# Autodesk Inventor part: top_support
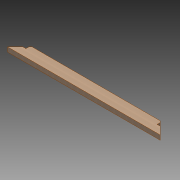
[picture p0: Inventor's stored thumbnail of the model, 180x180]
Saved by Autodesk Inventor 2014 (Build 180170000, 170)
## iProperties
Created: 2014-05
Part Number: top_support
Material: Maple
Document SubType Name: Modeling
Designer: t_emanb
Density: 1 g/cm^3
Appearance: Maple - Solid Natural Medium Gloss
Author: t_emanb
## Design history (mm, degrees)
sketch "Sketch1"
  geometry: L1 (0, 0)-(635, 0); L2 (635, 0)-(635, 635); L3 (635, 635)-(0, 635); L4 (0, 635)-(0, 0)
  constraints: 8 end point, 2 parallel, 1 horizontal, 1 perpendicular
  dimensions: "d0" = 635 distance of L1.start L1.end (= d1); "d1" = 635 distance of L3.end L1.start
extrude "Extrusion1" new body sketch "Sketch1" distance "d2" = 19.05; taper "d3" = 0 deg
sketch "Sketch2"
  geometry: L1 (0, 0)-(-635, 0) reference; L2 (-635, 0)-(-635, -635) reference; L3 (-635, -635)-(0, -635) reference; L4 (0, -635)-(0, 0) reference; L5 (-584.2, -50.8)-(-50.8, -50.8); L6 (-50.8, -50.8)-(-50.8, -584.2); L7 (-50.8, -584.2)-(-584.2, -584.2); L8 (-584.2, -584.2)-(-584.2, -50.8)
  constraints: 8 end point, 3 other
  dimensions: "d4" = 533.4 distance of L5.end L6.end
extrude "Extrusion2" cut sketch "Sketch2" stored distance "d5" = 12.7; taper "d6" = 0 deg
sketch "Sketch4"
  geometry: L1 (-584.2, -584.2)-(-584.2, -50.8) reference; L2 (-584.2, -50.8)-(-50.8, -50.8) reference; L3 (-50.8, -50.8)-(-50.8, -584.2) reference; L4 (0, 0)-(-635, 0) reference; L5 (-635, 0)-(-635, -635) reference; L6 (0, -635)-(0, 0) reference; L7 (-635, -635)-(-584.2, -584.2); L8 (-50.8, -584.2)-(0, -635)
  constraints: 4 end point, 1 perpendicular
extrude "Extrusion4" cut sketch "Sketch4" stored distance "d12" = 12.7; taper "d13" = 0 deg
workplane "Work Plane2"
  workplane "Work Plane1"
sketch "Sketch6"
  geometry: L1 (0, -50.8)-(0, 0) reference; L2 (19.05, -50.8)-(0, -50.8) reference; L3 (19.05, 0)-(19.05, -50.8) reference; L4 (0, 0)-(19.05, 0) reference; L5 (0, -38.1)-(6.35, -38.1); L6 (6.35, -38.1)-(6.35, -50.8); 1 further point
  constraints: 4 end point, 2 point on line, 1 parallel, 1 perpendicular
  dimensions: "d20" = 6.35 distance of L5.start L5.end; "d21" = 12.7 distance of L5.end L6.end
extrude "Extrusion6" cut sketch "Sketch6" stored distance "d22" = 12.7; taper "d23" = 0 deg
sketch "Sketch5"
  geometry: L1 (0, -635)-(-50.8, -584.2) reference; L2 (-50.8, -584.2)-(-584.2, -584.2) reference; L3 (-584.2, -584.2)-(-635, -635) reference; L4 (-635, -635)-(0, -635) reference; L5 (-317.5, -584.2)-(-317.5, -635); L6 (-31.75, -603.25)-(-44.45, -603.25); L7 (-44.45, -603.25)-(-44.45, -590.55); L8 (-590.55, -603.25)-(-590.55, -590.55); L9 (-603.25, -603.25)-(-590.55, -603.25); L10 (-603.25, -603.25)-(-590.55, -590.55); 1 further point
  constraints: 12 end point, 3 symmetric about line, 2 midpoint, 2 perpendicular, 2 point on line, 1 collinear
  dimensions: "d14" = 31.75 distance between parallel lines of L4 L6; "d15" = 44.45 distance from line of L1.start L7
extrude "Extrusion5" cut sketch "Sketch5" stored distance "d16" = 12.7; taper "d17" = 0 deg
body "Solid1"
node "Projected Loop1"
feature "쀀쁏"
other parameters: "d18" = 90 deg, "d19" = -317.5
